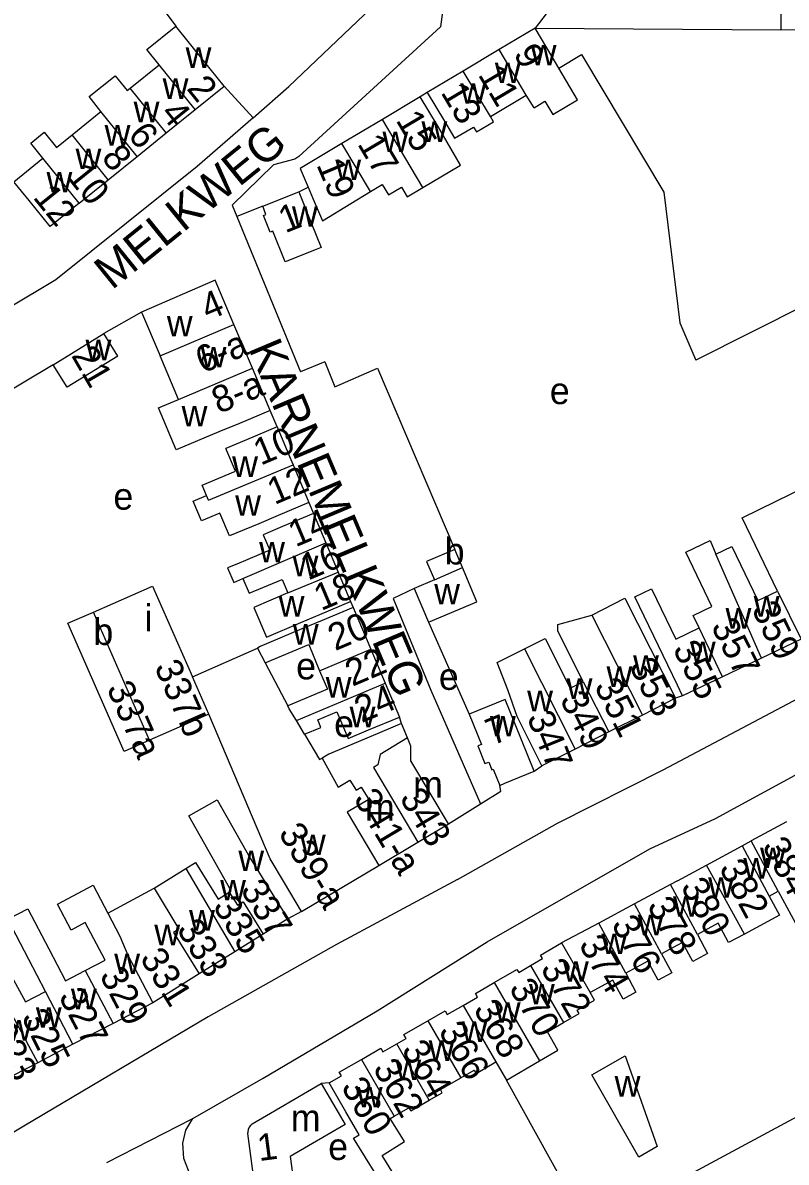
# Model space of a CAD drawing. Extents: x 163012 to 165277, y 382513 to 383987.
# Drawn here: x 163402 to 163516.3, y 383644.3 to 383815 of the extents above; entities that cross this region are included whole.
import ezdxf

# ---------------------------------------------------------------- set-up
doc = ezdxf.new("R2010")
doc.units = 0
for name, color, linetype in [('BLT_Basislijn', 7, 'Continuous'), ('BLT_Bebouwing', 7, 'Continuous'), ('BLT_Centroide', 7, 'Continuous'), ('BLT_Huisnummer', 7, 'Continuous'), ('BLT_Huisnummer_ tussenligend', 7, 'Continuous'), ('BLT_Huisnummer_reeks', 7, 'Continuous'), ('BLT_Onderverdeling_panden', 7, 'Continuous'), ('BLT_Straatnaam', 7, 'Continuous'), ('BLT_Vlakafsluiter', 7, 'Continuous')]:
    doc.layers.add(name, color=color, linetype=linetype)

msp = doc.modelspace()

# ---------------------------------------------------------------- linework, layer by layer
at = {"layer": 'BLT_Basislijn'}
for p, q in [((163515.88, 383842.69), (163515.47, 383813.9)), ((163480.36, 383816.3), (163478.7, 383814.16)), ((163478.7, 383814.16), (163515.47, 383813.9)), ((163568.95, 383813.77), (163515.47, 383813.9)), ((163432.15, 383805.47), (163436.46, 383800.74)), ((163462.55, 383804.54), (163461.5, 383803.87)), ((163443.29, 383789.64), (163444.72, 383790.33)), ((163437.91, 383787.51), (163434.03, 383785.96)), ((163519.33, 383772.77), (163502.73, 383764.43)), ((163447.21, 383764.17), (163443.56, 383762.67)), ((163447.21, 383764.17), (163448.69, 383760.45)), ((163440.06, 383754.44), (163439.01, 383756.92)), ((163444.83, 383743.12), (163445.49, 383741.45)), ((163460.59, 383730.25), (163457.44, 383728.75)), ((163451.05, 383728.3), (163451.43, 383727.39)), ((163462.72, 383725.18), (163468.8, 383711.43)), ((163500.76, 383714.16), (163499.7, 383713.79)), ((163458.69, 383710), (163458.37, 383710.98)), ((163478.57, 383702.86), (163479.71, 383703.68)), ((163470.51, 383697.96), (163473.56, 383699.85)), ((163473.56, 383699.85), (163473.4, 383700.74)), ((163465.73, 383694.98), (163470.51, 383697.96)), ((163443.72, 383681.84), (163441.65, 383680.74)), ((163447.86, 383656.17), (163446.68, 383656.07)), ((163485.71, 383636.26), (163474.39, 383656.6))]:
    msp.add_line(p, q, dxfattribs=at)
for points in [[(163691.8, 383838.07), (163676.87, 383840.68), (163510.41, 383850.53), (163478.47, 383853), (163475.35, 383851.32), (163474.04, 383848.58), (163474.12, 383846.38), (163474.97, 383844.79), (163474.33, 383836.09), (163472.16, 383827.71), (163469.76, 383821.83), (163468.5, 383821.46), (163464.99, 383817.7), (163464.52, 383814.35), (163443.33, 383794.96), (163442.73, 383794.54), (163439.5, 383793.72), (163433.33, 383787.67), (163434.03, 383785.96)], [(163436.46, 383800.74), (163441.8, 383805.45), (163456.17, 383819.14), (163459.83, 383824.14), (163461.5, 383828.2), (163462.54, 383831.79), (163463.81, 383838.1), (163463.49, 383841.12), (163461.26, 383843.15), (163458.87, 383843.6), (163420.65, 383845.4)], [(163419.06, 383821.52), (163419.56, 383821.31), (163421.35, 383819.26), (163424.91, 383814.46)], [(163482.24, 383808.2), (163485.64, 383810.21), (163497.95, 383789.61), (163500.35, 383770.03), (163502.73, 383764.43)], [(163467.08, 383686.66), (163482.06, 383695.06), (163497.86, 383703.08), (163529.23, 383719.71), (163691.55, 383804.36), (163698.23, 383808.79)], [(163427.43, 383650.86), (163437.95, 383656.9), (163455.03, 383666.99), (163471.53, 383677.31), (163495.84, 383691.23), (163505.72, 383695.8), (163549.29, 383719.48), (163576.55, 383733.91), (163700.36, 383799.41), (163713.52, 383805.75), (163715.26, 383807.23)], [(163436.46, 383800.74), (163428.08, 383793.47), (163406.94, 383776.46), (163372.44, 383755.87), (163359.51, 383750)], [(163434.03, 383785.96), (163443.56, 383762.67)], [(163419.77, 383771.64), (163414.13, 383768.41)], [(163406.55, 383763.74), (163378.18, 383746.79), (163350, 383732.45)], [(163448.69, 383760.45), (163455.1, 383763.26), (163466.69, 383736.07)], [(163457.44, 383728.75), (163463.06, 383715.01), (163470.51, 383697.96)], [(163467.08, 383686.66), (163448.94, 383676.91), (163429.74, 383666.09), (163402.15, 383649.68)], [(163485.71, 383636.26), (163495.05, 383641.57), (163495.75, 383641.62), (163496.81, 383640.02), (163497.28, 383640.02), (163554.26, 383670.71)], [(163440.05, 383577.02), (163439.01, 383577.29), (163438.07, 383577.85), (163437.35, 383578.5), (163436.86, 383579.42), (163435.68, 383600.04), (163430.96, 383632.29), (163426.08, 383644.86), (163425.95, 383647.16), (163426.37, 383649.07), (163427.43, 383650.86)], [(163402.15, 383649.68), (163399, 383647.82), (163395.81, 383646.04), (163392.58, 383644.32), (163389.32, 383642.67), (163386.01, 383641.1), (163382.68, 383639.6), (163379.31, 383638.17), (163375.91, 383636.82), (163372.49, 383635.54), (163369.03, 383634.33), (163365.55, 383633.21), (163362.05, 383632.15), (163358.52, 383631.18), (163356.75, 383630.73)]]:
    msp.add_lwpolyline(points, dxfattribs=at)
at = {"layer": 'BLT_Bebouwing'}
for p, q in [((163478.7, 383814.16), (163473.32, 383810.95)), ((163473.32, 383810.95), (163467.93, 383807.75)), ((163418.04, 383805.19), (163422.39, 383808.69)), ((163467.93, 383807.75), (163462.55, 383804.54)), ((163427.81, 383801.97), (163432.15, 383805.47)), ((163461.5, 383803.87), (163455.84, 383800.5)), ((163471.99, 383800.93), (163477.37, 383804.13)), ((163478.53, 383802.23), (163477.37, 383804.13)), ((163409.35, 383798.18), (163413.69, 383801.68)), ((163423.46, 383798.47), (163427.81, 383801.97)), ((163455.84, 383800.5), (163449.75, 383796.88)), ((163419.11, 383794.96), (163423.46, 383798.47)), ((163414.76, 383791.46), (163419.11, 383794.96)), ((163410.42, 383787.95), (163414.76, 383791.46)), ((163437.91, 383787.51), (163443.29, 383789.64)), ((163419.77, 383771.64), (163422.53, 383765.09)), ((163436.35, 383763.22), (163433.6, 383769.76)), ((163406.55, 383763.74), (163414.13, 383768.41)), ((163416.2, 383765.05), (163414.13, 383768.41)), ((163416.2, 383765.05), (163408.62, 383760.38)), ((163425.27, 383758.54), (163422.53, 383765.09)), ((163408.62, 383760.38), (163406.55, 383763.74)), ((163439.01, 383756.92), (163436.35, 383763.22)), ((163440.06, 383754.44), (163441.93, 383750)), ((163441.93, 383750), (163442.45, 383748.75)), ((163442.45, 383748.75), (163444.83, 383743.12)), ((163445.49, 383741.45), (163447.34, 383737.07)), ((163447.34, 383737.07), (163449.19, 383732.68)), ((163449.19, 383732.68), (163451.05, 383728.3)), ((163460.59, 383730.25), (163462.72, 383725.18)), ((163451.43, 383727.39), (163454.07, 383721.14)), ((163408.73, 383725.04), (163412.58, 383726.71)), ((163499.75, 383722.63), (163503.24, 383724.32)), ((163518.53, 383722.65), (163512.57, 383719.8)), ((163427.39, 383717.01), (163437.12, 383721.3)), ((163454.07, 383721.14), (163456.22, 383716.05)), ((163438.27, 383719.11), (163441.66, 383712.66)), ((163512.57, 383719.8), (163506.74, 383717.02)), ((163506.74, 383717.02), (163500.76, 383714.16)), ((163456.22, 383716.05), (163458.37, 383710.98)), ((163500.76, 383714.16), (163500, 383715.73)), ((163499.7, 383713.79), (163494.75, 383711.28)), ((163429.86, 383711.42), (163420.96, 383707.5)), ((163459.58, 383707.87), (163458.69, 383710)), ((163494.75, 383711.28), (163489.74, 383708.76)), ((163489.74, 383708.76), (163484.67, 383706.19)), ((163484.67, 383706.19), (163479.71, 383703.68)), ((163461.14, 383692.24), (163465.73, 383694.98)), ((163516.33, 383695.28), (163511.02, 383692.42)), ((163455.3, 383688.76), (163461.14, 383692.24)), ((163504.33, 383688.78), (163509.7, 383691.67)), ((163509.7, 383691.67), (163511.02, 383692.42)), ((163509.7, 383691.67), (163513.74, 383684.17)), ((163515.08, 383684.89), (163511.02, 383692.42)), ((163421.63, 383685.32), (163426.4, 383688.28)), ((163443.72, 383681.84), (163455.3, 383688.76)), ((163499.99, 383686.44), (163504.33, 383688.78)), ((163499.99, 383686.44), (163498.96, 383685.89)), ((163414.71, 383681.62), (163421.63, 383685.32)), ((163498.96, 383685.89), (163493.59, 383683)), ((163513.74, 383684.17), (163515.08, 383684.89)), ((163493.59, 383683), (163488.22, 383680.11)), ((163441.65, 383680.74), (163437.98, 383678.46)), ((163488.22, 383680.11), (163482.64, 383677.14)), ((163437.98, 383678.46), (163433.75, 383675.83)), ((163500, 383676.79), (163497.62, 383675.51)), ((163433.75, 383675.83), (163428.4, 383672.5)), ((163428.4, 383672.5), (163421.44, 383668.19)), ((163421.44, 383668.19), (163415.49, 383665.07)), ((163415.49, 383665.07), (163409.49, 383661.96)), ((163409.49, 383661.96), (163404.23, 383659.2)), ((163404.23, 383659.2), (163398.71, 383656.33)), ((163472.82, 383659.32), (163474.39, 383656.6)), ((163474.39, 383656.6), (163479.37, 383659.48)), ((163487.16, 383657.4), (163492.15, 383660.25)), ((163492.15, 383660.25), (163496.98, 383646.65)), ((163494.22, 383645.04), (163487.16, 383657.4)), ((163438.46, 383651.29), (163446.68, 383656.07)), ((163436.34, 383650.06), (163438.46, 383651.29)), ((163435.69, 383648.58), (163435.67, 383648.71)), ((163436.57, 383641.83), (163435.69, 383648.58)), ((163442.02, 383645.16), (163442.35, 383642.59)), ((163496.98, 383646.65), (163494.22, 383645.04))]:
    msp.add_line(p, q, dxfattribs=at)
for points in [[(163422.39, 383808.69), (163420.56, 383810.96), (163424.91, 383814.46)], [(163432.15, 383805.47), (163429.01, 383809.36), (163424.91, 383814.46)], [(163482.24, 383808.2), (163481.26, 383809.86), (163478.7, 383814.16)], [(163478.53, 383802.23), (163480.14, 383803.22), (163481.35, 383801.24), (163485.05, 383803.45), (163482.24, 383808.2)], [(163413.69, 383801.68), (163411.9, 383803.91), (163413.86, 383805.49), (163415.8, 383807.05), (163417.59, 383804.83), (163418.04, 383805.19)], [(163461.9, 383790.32), (163467.5, 383793.67), (163464.06, 383799.57), (163461.5, 383803.87)], [(163462.55, 383804.54), (163465.1, 383800.25), (163466.62, 383797.68), (163469.48, 383799.36), (163469.91, 383798.64), (163472.45, 383800.16), (163471.99, 383800.93)], [(163405, 383794.67), (163403.18, 383796.92), (163405.2, 383798.57), (163407.02, 383796.31), (163409.35, 383798.18)], [(163449.75, 383796.88), (163443.52, 383793.17), (163444.72, 383790.33)], [(163410.42, 383787.95), (163406.07, 383784.45), (163402.93, 383788.34), (163400.65, 383791.17), (163405, 383794.67)], [(163444.72, 383790.33), (163445.47, 383788.57), (163446.84, 383785.32), (163451.11, 383787.92), (163454.03, 383789.69)], [(163454.03, 383789.69), (163455.79, 383790.76), (163456.73, 383789.18), (163458.68, 383790.33), (163459.52, 383788.91), (163461.9, 383790.32)], [(163443.29, 383789.64), (163445.16, 383785), (163446.64, 383781.31), (163445.9, 383781.02), (163441.26, 383779.17)], [(163441.26, 383779.17), (163439.42, 383783.74), (163439, 383783.59), (163438, 383786.12), (163438.38, 383786.28), (163437.91, 383787.51)], [(163433.6, 383769.76), (163430.8, 383776.4), (163419.77, 383771.64)], [(163439.01, 383756.92), (163434.41, 383754.97), (163431.33, 383753.69), (163424.96, 383751.02), (163422.29, 383757.3), (163425.27, 383758.54)], [(163440.06, 383754.44), (163435.46, 383752.5), (163432.39, 383751.21)], [(163429.5, 383744.16), (163428.84, 383745.72), (163433.81, 383747.82), (163432.39, 383751.21)], [(163444.83, 383743.12), (163440.22, 383741.18), (163437.31, 383739.94), (163432.94, 383738.1), (163431.5, 383741.53), (163431.5, 383741.53), (163428.73, 383740.36), (163427.49, 383743.31), (163429.5, 383744.16)], [(163514.97, 383729.83), (163509.69, 383740.81), (163514.78, 383743.3), (163518.96, 383745.35)], [(163445.49, 383741.45), (163440.89, 383739.51), (163437.98, 383738.28), (163438.95, 383735.98), (163434.02, 383733.9), (163432.65, 383733.32), (163433.56, 383731.15), (163434.93, 383731.73)], [(163503.24, 383724.32), (163502.35, 383726.19), (163505.16, 383727.53), (163501.26, 383735.69), (163504.92, 383737.44), (163505.74, 383735.39)], [(163466.69, 383736.07), (163462.43, 383734.29), (163463.6, 383731.51)], [(163467.83, 383733.36), (163466.69, 383736.07)], [(163505.74, 383735.39), (163508.14, 383736.53), (163512.02, 383728.42), (163514.97, 383729.83)], [(163462.72, 383725.18), (163469.98, 383728.22), (163467.83, 383733.36)], [(163412.58, 383726.71), (163421.4, 383730.6), (163427.39, 383717.01)], [(163434.93, 383731.73), (163435.87, 383729.51), (163440.8, 383731.59), (163441.66, 383729.56)], [(163463.6, 383731.51), (163460.59, 383730.25)], [(163441.66, 383729.56), (163436.57, 383727.41), (163438.45, 383722.96), (163443.6, 383725.15), (163446.44, 383726.35), (163451.05, 383728.3)], [(163500, 383715.73), (163498.55, 383718.74), (163493.61, 383729), (163496.11, 383730.2), (163499.75, 383722.63)], [(163451.43, 383727.39), (163446.82, 383725.46), (163443.78, 383724.19), (163437.51, 383721.56), (163437.12, 383721.3)], [(163487.18, 383726.26), (163492.13, 383728.76), (163499.7, 383713.79)], [(163485.9, 383716.27), (163484.42, 383719.2), (163482.08, 383723.83), (163482.1, 383724.84), (163487.18, 383726.26)], [(163420.96, 383707.5), (163417.18, 383705.83), (163408.73, 383725.04)], [(163477.08, 383721.2), (163480.17, 383722.76), (163483.95, 383715.28), (163485.9, 383716.27)], [(163438.27, 383719.11), (163444.79, 383721.83), (163446.43, 383717.91)], [(163474.59, 383715.06), (163472.99, 383719.13), (163474, 383719.65), (163477.08, 383721.2)], [(163446.43, 383717.91), (163447.59, 383715.14), (163441.66, 383712.66)], [(163478.57, 383702.86), (163475.68, 383709.91), (163474.18, 383713.61), (163468.8, 383711.43)], [(163479.71, 383703.68), (163475.99, 383711.05), (163474.98, 383713.93)], [(163444.16, 383708.39), (163446.63, 383709.42), (163446.14, 383710.58), (163449, 383711.78), (163450.68, 383707.77), (163453.76, 383709.05), (163458.37, 383710.98)], [(163443.72, 383681.84), (163441.16, 383686.14), (163439, 383689.75), (163429.86, 383711.42)], [(163458.69, 383710), (163454.08, 383708.07), (163447.79, 383705.43), (163446.78, 383704.83)], [(163468.8, 383711.43), (163470.64, 383706.88), (163470.09, 383706.65), (163471.16, 383704), (163471.74, 383704.24), (163472.2, 383703.08), (163472.41, 383703.17), (163473.4, 383700.74)], [(163444.16, 383708.39), (163446.41, 383704.61), (163446.78, 383704.83)], [(163465.73, 383694.98), (163460.1, 383704.42), (163460.1, 383706.63), (163459.58, 383707.87)], [(163473.4, 383700.74), (163474.14, 383701.05), (163478.57, 383702.86)], [(163432.89, 383684.76), (163433.2, 383684.94), (163426.86, 383696.18), (163431.08, 383698.57), (163436.01, 383689.83), (163437.41, 383687.57), (163439.01, 383684.99), (163441.65, 383680.74)], [(163426.4, 383688.28), (163427.84, 383689.17), (163431.22, 383683.72), (163432.89, 383684.76)], [(163515.08, 383684.89), (163517.65, 383680.12), (163522.96, 383682.97), (163520.38, 383687.76)], [(163411.34, 383672.99), (163414.29, 383674.54), (163411.34, 383680.18), (163409.21, 383679.06), (163407.17, 383682.96), (163412.54, 383685.77), (163414.71, 383681.62)], [(163513.74, 383684.17), (163515.27, 383681.32), (163510.02, 383678.47)], [(163405.36, 383669.85), (163402.88, 383674.67), (163399.76, 383680.72), (163402.73, 383682.27), (163405.88, 383676.24), (163408.39, 383671.44), (163411.34, 383672.99)], [(163396.65, 383673.24), (163393.2, 383679.63), (163395.49, 383680.83), (163402.41, 383668.31), (163405.36, 383669.85)], [(163510.02, 383678.47), (163507.65, 383677.2), (163506.1, 383680.09), (163502.98, 383678.42)], [(163502.98, 383678.42), (163504.52, 383675.55), (163502.3, 383674.35), (163500.75, 383677.22), (163500, 383676.79)], [(163478.01, 383673.76), (163479.79, 383674.79), (163479.49, 383675.31), (163482.64, 383677.14)], [(163497.62, 383675.51), (163499.16, 383672.65), (163497.12, 383671.55), (163495.58, 383674.41), (163492.25, 383672.62)], [(163472.57, 383671.22), (163475.97, 383673.18), (163476.23, 383672.73), (163478.01, 383673.76)], [(163492.25, 383672.62), (163493.79, 383669.76), (163491.85, 383668.72), (163490.33, 383671.56), (163486.93, 383669.74)], [(163467.92, 383667.78), (163470.06, 383669.02), (163469.74, 383669.57), (163472.57, 383671.22)], [(163482.96, 383665.22), (163485.28, 383666.56), (163484.98, 383667.07), (163487.6, 383668.59), (163486.93, 383669.74)], [(163462.62, 383665.47), (163465.21, 383666.97), (163465.54, 383666.4), (163467.92, 383667.78)], [(163457.96, 383662.03), (163459.37, 383662.85), (163459.05, 383663.4), (163462.62, 383665.47)], [(163479.37, 383659.48), (163482.1, 383661.07), (163480.52, 383663.8), (163482.96, 383665.22)], [(163452.68, 383659.68), (163455.6, 383661.37), (163455.91, 383660.84), (163457.96, 383662.03)], [(163447.86, 383656.17), (163449.68, 383657.22), (163449.36, 383657.76), (163452.68, 383659.68)], [(163467.55, 383656.94), (163469.56, 383658.1), (163469.84, 383657.6), (163472.82, 383659.32)], [(163446.68, 383656.07), (163449.19, 383651.74), (163450.24, 383649.94), (163442.02, 383645.16)], [(163456.63, 383639.59), (163451.48, 383647.92), (163452.35, 383648.42), (163450.37, 383651.84), (163447.86, 383656.17)], [(163462.85, 383653.59), (163464.77, 383654.7), (163464.5, 383655.17), (163467.55, 383656.94)], [(163457.6, 383651.18), (163459.79, 383652.45), (163460.07, 383651.97), (163462.85, 383653.59)], [(163457.38, 383638.41), (163459.81, 383639.94), (163458, 383642.88), (163457.5, 383642.57), (163455.81, 383645.31), (163459.11, 383647.4), (163456.99, 383650.83), (163457.6, 383651.18)], [(163436.34, 383650.06), (163436.07, 383649.81), (163435.87, 383649.52), (163435.73, 383649.18), (163435.67, 383648.83), (163435.67, 383648.71)]]:
    msp.add_lwpolyline(points, dxfattribs=at)
at = {"layer": 'BLT_Onderverdeling_panden'}
for p, q in [((163477.37, 383804.13), (163473.32, 383810.95)), ((163427.81, 383801.97), (163422.39, 383808.69)), ((163471.99, 383800.93), (163467.93, 383807.75)), ((163423.46, 383798.47), (163418.04, 383805.19)), ((163419.11, 383794.96), (163413.69, 383801.68)), ((163461.9, 383790.32), (163455.84, 383800.5)), ((163414.76, 383791.46), (163409.35, 383798.18)), ((163454.03, 383789.69), (163449.75, 383796.88)), ((163410.42, 383787.95), (163405, 383794.67)), ((163422.53, 383765.09), (163433.6, 383769.76)), ((163425.27, 383758.54), (163436.35, 383763.22)), ((163434.93, 383731.73), (163447.34, 383737.07)), ((163512.57, 383719.8), (163505.74, 383735.39)), ((163441.66, 383729.56), (163449.19, 383732.68)), ((163463.6, 383731.51), (163467.83, 383733.36)), ((163514.97, 383729.83), (163518.53, 383722.65)), ((163420.96, 383707.5), (163412.58, 383726.71)), ((163487.18, 383726.26), (163494.75, 383711.28)), ((163506.74, 383717.02), (163503.24, 383724.32)), ((163437.12, 383721.3), (163438.27, 383719.11)), ((163446.43, 383717.91), (163454.07, 383721.14)), ((163477.08, 383721.2), (163484.67, 383706.19)), ((163429.86, 383711.42), (163427.39, 383717.01)), ((163442.94, 383710.44), (163456.22, 383716.05)), ((163485.9, 383716.27), (163489.74, 383708.76)), ((163474.98, 383713.93), (163474.59, 383715.06)), ((163444.16, 383708.39), (163442.94, 383710.44)), ((163454.48, 383703.41), (163461.14, 383692.24)), ((163426.4, 383688.28), (163433.75, 383675.83)), ((163510.02, 383678.47), (163504.33, 383688.78)), ((163502.98, 383678.42), (163498.96, 383685.89)), ((163497.62, 383675.51), (163493.59, 383683)), ((163492.25, 383672.62), (163488.22, 383680.11)), ((163482.64, 383677.14), (163486.93, 383669.74)), ((163396.65, 383673.24), (163404.23, 383659.2)), ((163411.34, 383672.99), (163415.49, 383665.07)), ((163478.01, 383673.76), (163482.96, 383665.22)), ((163472.57, 383671.22), (163479.37, 383659.48)), ((163409.49, 383661.96), (163405.36, 383669.85)), ((163467.92, 383667.78), (163472.82, 383659.32)), ((163462.62, 383665.47), (163467.55, 383656.94)), ((163462.85, 383653.59), (163457.96, 383662.03)), ((163452.68, 383659.68), (163457.6, 383651.18))]:
    msp.add_line(p, q, dxfattribs=at)
for points in [[(163429.8, 383743.46), (163442.45, 383748.75)], [(163429.8, 383743.46), (163429.5, 383744.16)], [(163442.94, 383710.44), (163441.88, 383712.23), (163441.66, 383712.66)], [(163459.58, 383707.87), (163455.51, 383705.36), (163455.16, 383703.8), (163454.48, 383703.41)], [(163446.78, 383704.83), (163449.21, 383700.48), (163450.97, 383701.53), (163451.88, 383700.01), (163452.66, 383700.47), (163453.77, 383698.62), (163450.55, 383696.71), (163455.3, 383688.76)], [(163421.63, 383685.32), (163425.34, 383679.22), (163424.54, 383678.72), (163428.4, 383672.5)], [(163432.89, 383684.76), (163434.11, 383682.79), (163434.96, 383683.31), (163437.98, 383678.46)], [(163414.71, 383681.62), (163416.52, 383678.16), (163417.7, 383675.32), (163421.44, 383668.19)]]:
    msp.add_lwpolyline(points, dxfattribs=at)
at = {"layer": 'BLT_Vlakafsluiter'}
msp.add_line((163414.54, 383644.24), (163427.43, 383650.86), dxfattribs=at)

# ---------------------------------------------------------------- texts
at = {"layer": 'BLT_Centroide'}
for s, p in [('w', (163426.36, 383808.22)), ('w', (163478.03, 383808.59)), ('w', (163472.66, 383805.94)), ('w', (163422.92, 383803.58)), ('w', (163467.5, 383802.84)), ('w', (163418.58, 383800.08)), ('w', (163414.23, 383796.58)), ('w', (163461.67, 383797.14)), ('w', (163455.83, 383795.61)), ('w', (163409.88, 383793.06)), ('w', (163448.78, 383791.41)), ('w', (163405.53, 383789.56)), ('w', (163442.28, 383784.41)), ('w', (163423.55, 383768)), ('w', (163411.38, 383764.41)), ('w', (163428.61, 383763.35)), ('e', (163480.89, 383757.85)), ('w', (163425.76, 383754.5)), ('w', (163433.33, 383746.94)), ('e', (163415.55, 383742.04)), ('w', (163433.78, 383741.13)), ('b', (163465.15, 383733.83)), ('w', (163437.37, 383734.13)), ('w', (163442.37, 383732.06)), ('w', (163463.58, 383727.86)), ('w', (163440.29, 383726.02)), ('w', (163511.42, 383726.02)), ('i', (163420.22, 383723.83)), ('w', (163507.2, 383724.23)), ('b', (163412.55, 383721.77)), ('w', (163442.41, 383721.82)), ('w', (163501.86, 383719.22)), ('e', (163442.91, 383716.62)), ('w', (163489.38, 383715.5)), ('w', (163493.36, 383717.16)), ('w', (163447.34, 383713.9)), ('e', (163464.28, 383715.05)), ('w', (163483.41, 383713.69)), ('w', (163477.5, 383711.85)), ('w', (163450.92, 383709.45)), ('e', (163448.6, 383708)), ('w', (163471.93, 383708.07)), ('m', (163460.42, 383698.89)), ('m', (163453.21, 383695.44)), ('w', (163443.48, 383690.3)), ('w', (163512.36, 383688.36)), ('w', (163434.25, 383687.91)), ('w', (163509.86, 383686.77)), ('w', (163431.53, 383683.52)), ('w', (163504.59, 383683.92)), ('w', (163499.33, 383681.06)), ('w', (163426.88, 383678.98)), ('w', (163494.05, 383678.28)), ('w', (163421.67, 383676.8)), ('w', (163488.61, 383675.47)), ('w', (163415.67, 383672.47)), ('w', (163482.86, 383671.33)), ('w', (163477.77, 383667.94)), ('w', (163409.19, 383667.2)), ('w', (163403.94, 383664.44)), ('w', (163472.66, 383665.19)), ('w', (163399.47, 383662.5)), ('w', (163467.66, 383662.31)), ('w', (163462.75, 383659.48)), ('w', (163457.77, 383656.59)), ('w', (163490.59, 383654.12)), ('w', (163452, 383652.51)), ('m', (163442.11, 383648.94)), ('e', (163447.71, 383644.63))]:
    msp.add_text(s, height=4, dxfattribs=at).set_placement(p)
at = {"layer": 'BLT_Huisnummer'}
for s, rotation, p in [('9', 300.7421, (163475.36, 383810.32)), ('2', 308.8667, (163426.4, 383805.09)), ('13', 300.7002, (163464.48, 383804.55)), ('15', 300.7002, (163457.75, 383800.39)), ('6', 308.865, (163417.58, 383798.09)), ('19', 292.8716, (163445.9, 383793.72)), ('12', 308.8638, (163403.39, 383788.8)), ('1', 21.7121, (163441.27, 383783.42)), ('4', 22.8796, (163429.7, 383770.31)), ('21', 300.1408, (163409.17, 383765.14)), ('10', 22.8687, (163437.59, 383748.61)), ('12', 22.8989, (163439.66, 383742.72)), ('14', 22.8989, (163442.81, 383736.38)), ('18', 22.8989, (163446.64, 383726.84)), ('359', 295.6063, (163511.04, 383727.19)), ('20', 22.9238, (163448.74, 383720.84)), ('355', 296.8098, (163499.23, 383721.2)), ('337b', 293.7962, (163421.63, 383718.51)), ('353', 296.8098, (163492.71, 383718.63)), ('337a', 293.7962, (163414.48, 383715.32)), ('24', 22.6825, (163452.69, 383710.05)), ('347', 292.2056, (163477.41, 383710.95)), ('7', 22.2561, (163472.32, 383706.69)), ('343', 300.8374, (163458.31, 383698.86)), ('384', 298.3094, (163512.6, 383691.68)), ('337', 301.8322, (163434.48, 383685.1)), ('380', 298.2369, (163500.42, 383685.61)), ('376', 298.2378, (163490.04, 383679.98)), ('331', 301.8277, (163419.43, 383674.85)), ('372', 300.099, (163479.41, 383673.34)), ('327', 297.6571, (163407.27, 383669.14)), ('368', 300.094, (163469.37, 383667.22)), ('323', 296.3076, (163396.8, 383664.12)), ('364', 300.0945, (163458.6, 383661.17)), ('360', 300.1575, (163449.56, 383655.59)), ('1', 7.4331, (163437.35, 383644.45))]:
    msp.add_text(s, height=4, rotation=rotation, dxfattribs=at).set_placement(p)
at = {"layer": 'BLT_Huisnummer_ tussenligend'}
for s, rotation, p in [('11', 300.7421, (163470.06, 383807.21)), ('4', 308.8667, (163422.43, 383801.34)), ('17', 300.7002, (163452, 383796.84)), ('8', 308.865, (163413.63, 383794.72)), ('10', 308.865, (163408.4, 383791.95)), ('16', 22.8989, (163444.66, 383731.39)), ('357', 296.8098, (163504.96, 383724.58)), ('22', 22.9238, (163451.32, 383715.5)), ('351', 296.8208, (163487.48, 383715.6)), ('349', 296.8208, (163482.33, 383713.63)), ('382', 298.2369, (163506.16, 383688.37)), ('335', 301.8277, (163430.35, 383682.65)), ('378', 298.2378, (163495.39, 383682.75)), ('333', 301.8277, (163424.93, 383679.19)), ('374', 300.099, (163485.14, 383676.91)), ('329', 297.6571, (163413.4, 383672.3)), ('370', 300.094, (163474.7, 383670.39)), ('325', 296.3076, (163401.71, 383666.06)), ('366', 300.0945, (163464.14, 383663.94)), ('362', 300.1575, (163454.32, 383658.35))]:
    msp.add_text(s, height=4, rotation=rotation, dxfattribs=at).set_placement(p)
at = {"layer": 'BLT_Huisnummer_reeks'}
for s, rotation, p in [('6-a', 22.8796, (163428.91, 383762.41)), ('8-a', 22.7177, (163431.33, 383756.36)), ('341-a', 300.8399, (163451.42, 383698.77)), ('339-a', 300.8377, (163440.18, 383693.62))]:
    msp.add_text(s, height=4, rotation=rotation, dxfattribs=at).set_placement(p)
at = {"layer": 'BLT_Straatnaam'}
for s, rotation, p in [('MELKWEG', 39.0287, (163415.32, 383774.86)), ('KARNEMELKWEG', 292.8757, (163435.71, 383766.25))]:
    msp.add_text(s, height=5, rotation=rotation, dxfattribs=at).set_placement(p)

doc.saveas('drawing.dxf')
